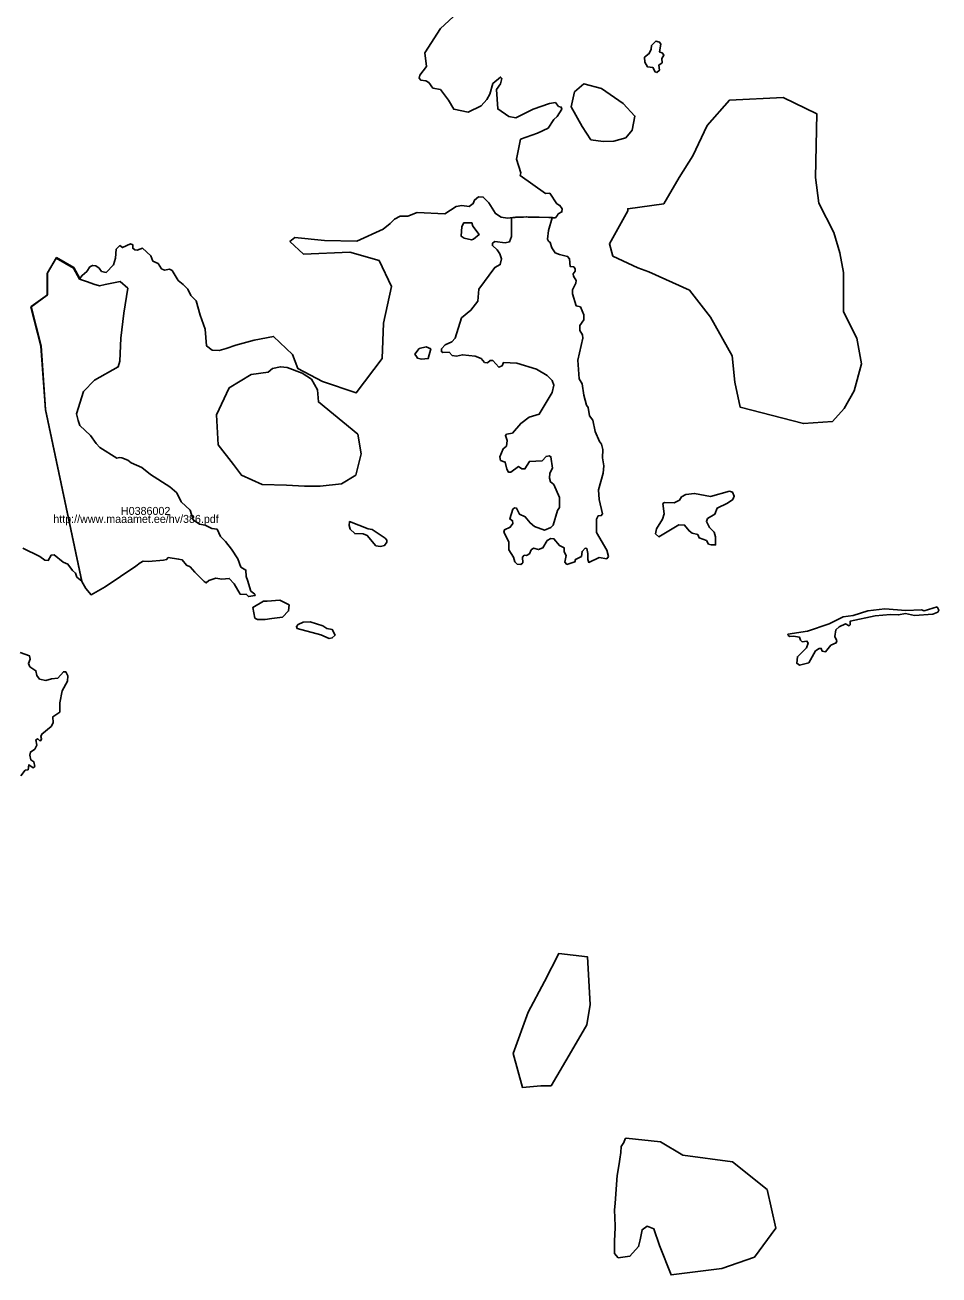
# Model space of a CAD drawing. Extents: x 369010 to 739155, y 6377141 to 6634081.
# Drawn here: x 449202 to 452056, y 6474923 to 6478828 of the extents above; entities that cross this region are included whole.
import ezdxf

# ---------------------------------------------------------------- set-up
doc = ezdxf.new("R2010")
doc.units = 0
for name, color, linetype in [('H_LINK', 7, 'Continuous'), ('H_PIIR', 7, 'Continuous'), ('H_TUNNUS', 7, 'Continuous')]:
    doc.layers.add(name, color=color, linetype=linetype)

msp = doc.modelspace()

# ---------------------------------------------------------------- linework, layer by layer
at = {"layer": 'H_PIIR'}
for points in [[(450579.291, 6478890.1741), (450499.9159, 6478817.4136), (450451.1638, 6478740.6622), (450455.7538, 6478698.1322), (450435.6438, 6478671.3221), (450432.9637, 6478662.1321), (450437.9438, 6478656.0022), (450454.0338, 6478654.0821), (450463.2238, 6478648.3422), (450476.2437, 6478630.3321), (450499.6138, 6478626.5022), (450524.8938, 6478593.5522), (450540.9264, 6478564.736), (450585.9839, 6478556.0122), (450626.3939, 6478575.5521), (450644.7837, 6478595.8622), (450654.3538, 6478611.5622), (450662.7839, 6478645.2821), (450687.2938, 6478665.5821), (450691.5137, 6478660.6022), (450687.2938, 6478644.5122), (450674.2739, 6478626.5022), (450678.51, 6478566.0589), (450713.3437, 6478542.6021), (450734.9838, 6478538.3821), (450788.9937, 6478565.5821), (450839.9061, 6478583.2568), (450858.427, 6478585.9027), (450868.6739, 6478573.6321), (450876.7137, 6478571.7122), (450878.2438, 6478565.5821), (450863.6938, 6478541.8322), (450853.3538, 6478532.6421), (450835.7337, 6478506.2021), (450802.2137, 6478489.7322), (450750.1138, 6478470.9621), (450737.2838, 6478409.2821), (450750.3137, 6478366.7622), (450748.7838, 6478357.5622), (450827.4938, 6478301.6422), (450840.8937, 6478302.7922), (450863.1138, 6478269.4622), (450872.6939, 6478264.4821), (450879.9638, 6478253.3721), (450878.8238, 6478244.1721), (450867.3238, 6478237.6622), (450864.7682, 6478234.0679), (450858.4182, 6478225.3366), (450848.9297, 6478226.0923), (450849.0221, 6478226.4048), (450843.2216, 6478226.547), (450838.4862, 6478226.9241), (450808.059, 6478227.5856), (450798.6339, 6478227.6397), (450773.6374, 6478228.2524), (450768.1069, 6478228.5116), (450758.5466, 6478228.2762), (450747.3452, 6478228.1151), (450744.5903, 6478227.8939), (450734.5047, 6478227.5856), (450708.7437, 6478224.6321), (450689.2037, 6478227.7022), (450671.9739, 6478238.8122), (450650.5237, 6478272.1422), (450633.2839, 6478290.5321), (450618.9239, 6478290.9121), (450605.9038, 6478281.3321), (450601.6838, 6478270.2221), (450589.0438, 6478261.4122), (450566.8337, 6478264.4721), (450548.8238, 6478260.6422), (450513.0138, 6478238.0421), (450427.2037, 6478242.2622), (450398.2937, 6478230.7722), (450373.7738, 6478230.3921), (450356.1538, 6478221.5822), (450342.7883, 6478207.7666), (450320.5633, 6478189.7749), (450238.0131, 6478152.7331), (450137.4712, 6478154.8498), (450045.3961, 6478164.3748), (450029.521, 6478151.6748), (450071.8544, 6478112.5164), (450216.8464, 6478118.8664), (450307.8632, 6478092.408), (450347.0217, 6478010.9162), (450321.6216, 6477896.616), (450317.3883, 6477786.5491), (450236.9548, 6477678.5989), (450131.1212, 6477714.5823), (450053.8627, 6477754.799), (450037.9877, 6477799.2491), (449978.7209, 6477855.3409), (449918.3958, 6477843.6992), (449860.1874, 6477827.8242), (449830.554, 6477817.2408), (449808.3289, 6477810.8908), (449787.1622, 6477811.9491), (449769.1705, 6477825.7075), (449764.9372, 6477877.5659), (449749.0621, 6477922.016), (449736.9738, 6477966.4322), (449719.7338, 6477982.9121), (449711.3039, 6478002.8322), (449696.3638, 6478017.7722), (449680.8538, 6478030.0322), (449662.0837, 6478060.6821), (449653.6638, 6478065.6622), (449637.5738, 6478062.2122), (449628.7639, 6478066.4321), (449617.6537, 6478082.5222), (449601.5637, 6478090.5622), (449594.8638, 6478106.6522), (449568.8239, 6478130.4022), (449552.7338, 6478125.0422), (449545.4538, 6478125.4221), (449538.9438, 6478130.4022), (449538.5538, 6478141.5121), (449532.0438, 6478144.9621), (449507.1538, 6478132.7022), (449498.7238, 6478138.8321), (449487.2338, 6478127.7221), (449484.5539, 6478099.7522), (449478.9938, 6478078.6721), (449455.6237, 6478054.9221), (449441.4538, 6478058.3721), (449433.7939, 6478067.9522), (449423.4538, 6478075.2221), (449413.1138, 6478077.1422), (449405.0638, 6478072.9321), (449395.1039, 6478058.3721), (449380.5537, 6478045.7321), (449373.4638, 6478036.1522), (449354.9038, 6478070.4775), (449300.9137, 6478101.7275), (449272.5038, 6478053.4276), (449272.5038, 6477985.2274), (449221.3537, 6477948.2774), (449252.6039, 6477826.0876), (449266.8138, 6477627.1775), (449380.2638, 6477091.0276), (449380.3405, 6477090.6648), (449379.6038, 6477090.2221), (449364.0838, 6477103.2522), (449359.8739, 6477115.5122), (449350.6839, 6477123.5522), (449336.5038, 6477144.2422), (449321.1837, 6477150.3721), (449293.6039, 6477172.5922), (449283.6437, 6477171.4422), (449274.8338, 6477155.3521), (449263.7338, 6477156.5022), (449248.9837, 6477167.9922), (449195.7438, 6477194.0521)], [(449187.7038, 6476868.0321), (449216.8239, 6476856.9222), (449218.5439, 6476846.9521), (449212.7939, 6476833.1622), (449217.0138, 6476823.2021), (449236.5438, 6476810.9421), (449238.8438, 6476796.3822), (449247.6538, 6476784.5121), (449267.5739, 6476780.2922), (449285.5738, 6476785.2722), (449304.7238, 6476787.5722), (449322.3439, 6476807.4921), (449330.0038, 6476807.1121), (449336.1337, 6476794.8521), (449334.6038, 6476778.3822), (449318.1338, 6476747.7321), (449311.4339, 6476710.9622), (449310.6638, 6476681.4622), (449289.5938, 6476667.2821), (449290.3638, 6476647.7421), (449283.8538, 6476637.0222), (449254.9339, 6476612.8922), (449251.8637, 6476604.8522), (449254.1637, 6476598.3322), (449252.2438, 6476593.3522), (449248.4137, 6476592.2022), (449242.2938, 6476598.3322), (449236.5438, 6476594.5022), (449239.6038, 6476578.7922), (449233.4837, 6476566.1522), (449219.3038, 6476556.5721), (449217.0038, 6476546.6122), (449220.8439, 6476532.4421), (449229.6538, 6476526.6921), (449233.4837, 6476512.1321), (449228.1138, 6476507.5421), (449214.3238, 6476517.1122), (449212.0337, 6476501.4122), (449203.2238, 6476500.6421), (449189.6237, 6476482.2521)]]:
    msp.add_lwpolyline(points, dxfattribs=at)
for points in [[(451174.9632, 6478679.4431), (451169.9981, 6478681.4292), (451163.0469, 6478695.166), (451145.8345, 6478697.4831), (451137.3938, 6478712.3784), (451136.5662, 6478727.2738), (451151.4616, 6478738.859), (451158.0819, 6478752.5959), (451158.7438, 6478764.0156), (451171.8186, 6478777.918), (451183.7349, 6478774.7734), (451187.5415, 6478768.3188), (451183.404, 6478744.4862), (451193.3341, 6478740.3485), (451197.4718, 6478734.225), (451191.3481, 6478723.4672), (451192.5066, 6478710.0614), (451181.7489, 6478702.7792), (451183.404, 6478686.7252)], [(450907.375, 6478572.6735), (450917.9584, 6478618.9757), (450947.0626, 6478644.1111), (451002.6252, 6478629.559), (451070.0941, 6478583.2568), (451107.1358, 6478543.5693), (451097.8754, 6478499.9129), (451078.0316, 6478476.1004), (451040.9899, 6478465.517), (451007.9169, 6478464.1941), (450969.5522, 6478469.4858), (450941.7709, 6478510.4963)], [(451196.8297, 6478268.9312), (451245.5132, 6478351.4814), (451287.8466, 6478419.2148), (451332.2967, 6478514.465), (451402.1468, 6478592.7819), (451569.3638, 6478601.2485), (451675.1974, 6478550.4484), (451670.964, 6478351.4814), (451681.5474, 6478271.0479), (451728.1141, 6478180.031), (451747.1642, 6478116.5309), (451757.7475, 6478055.1474), (451757.7475, 6477932.3805), (451800.081, 6477849.8304), (451814.8976, 6477769.3969), (451791.6143, 6477684.73), (451759.8642, 6477629.6966), (451723.8808, 6477589.4798), (451632.864, 6477583.1298), (451436.0136, 6477633.9299), (451419.0802, 6477712.2468), (451410.6135, 6477794.7969), (451342.88, 6477915.4472), (451277.2632, 6478000.114), (451150.263, 6478057.2641), (451116.3963, 6478069.9641), (451038.0794, 6478105.9475), (451027.4961, 6478144.0476), (451084.6462, 6478247.7645), (451084.6462, 6478254.1145)], [(450669.6796, 6478151.8163), (450701.4563, 6478147.1823), (450715.6896, 6478151.1544), (450721.0109, 6478166.8884), (450722.0031, 6478187.3936), (450721, 6478226), (450744.5903, 6478227.8939), (450751.0738, 6478228.0921), (450758.5466, 6478228.2762), (450767.4454, 6478228.4041), (450773.6374, 6478228.2524), (450785.0402, 6478227.7179), (450798.6339, 6478227.6397), (450843.2216, 6478226.547), (450848.9297, 6478226.0923), (450837.0971, 6478186.0707), (450833.7898, 6478159.2816), (450837.4278, 6478152.9977), (450842.1988, 6478148.8958), (450846.9984, 6478132.3454), (450857.7563, 6478116.788), (450871.493, 6478110.6643), (450896.4201, 6478105.1442), (450903.0402, 6478097.5311), (450904.8607, 6478073.3675), (450916.115, 6478072.2089), (450920.2526, 6478066.0853), (450920.2526, 6478059.1342), (450914.4599, 6478050.3625), (450915.2874, 6478043.0802), (450923.2317, 6478030.3364), (450922.9006, 6478021.5647), (450911.9773, 6478000.5456), (450911.9773, 6477988.6294), (450923.8936, 6477950.398), (450936.9685, 6477947.5844), (450947.2297, 6477922.4278), (450947.2297, 6477907.036), (450934.6514, 6477888.996), (450934.4859, 6477873.2731), (450943.5886, 6477860.3639), (450944.7472, 6477850.2681), (450928.1968, 6477780.9219), (450932.9964, 6477722.83), (450942.2646, 6477707.1071), (450946.8988, 6477671.3583), (450955.8359, 6477640.74), (450961.1321, 6477632.7959), (450965.4351, 6477606.6463), (450975.6964, 6477594.0679), (450982.9785, 6477557.988), (450995.8879, 6477527.0388), (451002.8391, 6477518.5981), (451006.6456, 6477501.7166), (451006.1492, 6477476.3945), (451010.1213, 6477451.0724), (451007.3076, 6477428.0674), (450993.4054, 6477375.6025), (450995.7225, 6477346.1429), (451005.6526, 6477300.9604), (451001.846, 6477295.4987), (450991.9158, 6477294.5057), (450986.9506, 6477284.41), (450987.1162, 6477242.3718), (451019.7205, 6477187.921), (451024.1891, 6477167.564), (451018.893, 6477160.7785), (450995.0604, 6477164.0885), (450962.9526, 6477149.1931), (450959.4771, 6477157.9648), (450960.3046, 6477177.4943), (450957.16, 6477192.5552), (450951.5327, 6477193.2172), (450941.9335, 6477183.618), (450939.6165, 6477168.0606), (450921.5765, 6477158.4614), (450919.2596, 6477150.6827), (450894.7649, 6477143.0694), (450887.6482, 6477150.3517), (450891.9514, 6477170.7086), (450885.8277, 6477181.7974), (450885.8277, 6477194.8722), (450871.2635, 6477202.1544), (450854.051, 6477223.1734), (450843.9552, 6477223.5044), (450832.5354, 6477217.3809), (450819.4607, 6477195.2033), (450806.0548, 6477189.0797), (450790.0008, 6477193.2172), (450783.3807, 6477188.2521), (450777.5882, 6477175.6738), (450768.3199, 6477170.7086), (450761.5342, 6477171.3706), (450755.4107, 6477166.0746), (450756.4036, 6477148.0347), (450750.7765, 6477142.7385), (450738.8603, 6477143.897), (450731.9091, 6477151.5102), (450728.1024, 6477165.247), (450713.2071, 6477188.2521), (450713.2071, 6477213.2431), (450697.8153, 6477244.1925), (450699.4703, 6477251.1437), (450717.8412, 6477259.5843), (450725.7854, 6477270.3421), (450725.1233, 6477279.1138), (450716.1862, 6477285.2375), (450726.1163, 6477315.1937), (450730.585, 6477320.1588), (450737.5362, 6477318.5037), (450746.3079, 6477299.8017), (450764.3478, 6477291.3612), (450779.7396, 6477272.6592), (450793.8075, 6477261.4049), (450824.4257, 6477249.9851), (450844.6173, 6477258.0947), (450851.8994, 6477265.377), (450865.6362, 6477311.718), (450871.7599, 6477320.4899), (450871.0978, 6477352.2666), (450853.5544, 6477392.1529), (450843.6243, 6477400.5937), (450839.8177, 6477412.8411), (450840.9761, 6477427.7364), (450849.7478, 6477443.4593), (450844.7827, 6477479.0427), (450839.4866, 6477482.5182), (450829.5564, 6477480.2011), (450817.1436, 6477466.4644), (450777.4227, 6477464.4782), (450763.1892, 6477441.1423), (450753.59, 6477441.1423), (450743.1633, 6477448.4244), (450719.3307, 6477431.212), (450712.0486, 6477431.212), (450706.7524, 6477440.4802), (450702.1183, 6477462.6577), (450687.5539, 6477467.6228), (450684.9059, 6477479.0427), (450695.9946, 6477504.3648), (450706.2559, 6477512.4744), (450708.242, 6477530.5144), (450702.4492, 6477545.4097), (450705.9249, 6477549.5473), (450724.2958, 6477552.6919), (450750.6111, 6477583.3101), (450776.9261, 6477603.1706), (450808.0408, 6477612.1079), (450848.7548, 6477680.2955), (450853.389, 6477702.8041), (450848.4239, 6477717.3683), (450832.3699, 6477733.0912), (450799.4346, 6477752.9517), (450737.8671, 6477772.1503), (450696.9876, 6477774.1362), (450692.3536, 6477763.0475), (450681.5958, 6477759.0754), (450662.8938, 6477779.929), (450654.4531, 6477779.929), (450646.84, 6477772.9778), (450637.2408, 6477773.6398), (450626.6484, 6477786.7145), (450607.9464, 6477793.3348), (450568.0601, 6477797.8033), (450550.0201, 6477793.9967), (450535.7868, 6477795.9828), (450527.0151, 6477805.9131), (450507.3201, 6477804.7545), (450502.686, 6477807.8991), (450503.1826, 6477816.6707), (450514.2713, 6477828.9181), (450534.9593, 6477838.0207), (450545.2205, 6477849.2751), (450565.2464, 6477912.8286), (450594.8717, 6477936.9922), (450616.7183, 6477965.6243), (450619.6972, 6478002.8627), (450669.3484, 6478070.7195), (450686.5609, 6478079.4912), (450690.3675, 6478097.8621), (450685.0713, 6478112.7574), (450676.9617, 6478125.5012), (450661.7354, 6478139.238), (450662.0663, 6478146.5203)], [(450566.0618, 6478198.5519), (450572.4118, 6478209.6644), (450597.8119, 6478209.6644), (450600.9869, 6478200.1394), (450620.0369, 6478173.1518), (450602.5744, 6478158.8643), (450596.2244, 6478157.2768), (450573.9993, 6478162.0393), (450564.4743, 6478168.3893)], [(449379.5467, 6477089.0773), (449379.47, 6477089.4401), (449266.02, 6477625.59), (449251.8101, 6477824.5001), (449220.5599, 6477946.6899), (449271.71, 6477983.6399), (449271.71, 6478051.8401), (449300.1199, 6478100.14), (449354.11, 6478068.89), (449372.7, 6478034.4899), (449372.7126, 6478034.4668), (449397.8939, 6478025.3184), (449417.7377, 6478018.9684), (449435.3841, 6478013.7056), (449452.6627, 6478017.3809), (449499.9571, 6478026.8728), (449523.1082, 6478005.7061), (449511.2019, 6477927.6539), (449501.0816, 6477850.1969), (449498.3034, 6477777.5687), (449492.7472, 6477760.1061), (449418.9283, 6477718.831), (449385.1938, 6477683.5091), (449362.9688, 6477612.8652), (449368.1282, 6477593.0214), (449373.15, 6477576.92), (449407.0126, 6477545.7221), (449424.38, 6477520.8046), (449436.2599, 6477508.1646), (449488.73, 6477475.2146), (449497.73, 6477477.1346), (449505.0099, 6477476.3746), (449523.78, 6477468.7047), (449533.3601, 6477459.8947), (449567.06, 6477445.3346), (449593.8799, 6477424.2647), (449654.6, 6477385.5647), (449676.4301, 6477366.7946), (449690.2199, 6477338.8247), (449717.8, 6477312.0146), (449726.99, 6477282.5146), (449747.1, 6477268.7246), (449765.11, 6477265.6647), (449786.17, 6477254.9346), (449801.88, 6477253.0246), (449812.6001, 6477230.0346), (449828.6899, 6477214.7147), (449847.2701, 6477190.1846), (449867.19, 6477160.3046), (449876.77, 6477134.6347), (449892.0899, 6477125.0546), (449892.47, 6477105.1347), (449897.03, 6477093.5047), (449907.7901, 6477059.5447), (449920.4299, 6477049.9646), (449920.82, 6477046.1346), (449900.52, 6477042.6846), (449894.3899, 6477049.2047), (449873.6999, 6477050.3447), (449855.3201, 6477082.5346), (449840.38, 6477099.3847), (449816.82, 6477097.0847), (449798.0499, 6477099.7646), (449776.6, 6477092.8646), (449768.1701, 6477085.2046), (449761.66, 6477089.8046), (449732.55, 6477118.9147), (449717.9901, 6477135.3946), (449706.5001, 6477140.3747), (449693.48, 6477157.2247), (449681.8, 6477159.5247), (449649.62, 6477164.1247), (449644.26, 6477157.9946), (449634.3001, 6477156.4647), (449588.1401, 6477152.2446), (449571.2899, 6477153.0147), (449561.9469, 6477147.5945), (449548.7177, 6477137.6726), (449452.806, 6477072.8495), (449408.4882, 6477048.3755), (449391.9518, 6477068.2193)], [(450432.7116, 6477817.5511), (450454.9366, 6477822.3136), (450469.2241, 6477815.9636), (450461.2866, 6477785.8011), (450440.6491, 6477784.2136), (450427.949, 6477787.3886), (450424.774, 6477792.1511), (450420.0115, 6477800.0886)], [(449961.2584, 6477743.1573), (449975.5459, 6477755.0636), (450000.1522, 6477760.6199), (450020.7898, 6477758.2386), (450067.8857, 6477740.2469), (450096.4607, 6477721.1969), (450116.0399, 6477687.8593), (450118.6858, 6477650.8176), (450241.9819, 6477549.7465), (450252.3006, 6477488.6276), (450235.6319, 6477421.9525), (450190.388, 6477394.4358), (450124.242, 6477387.8212), (450075.294, 6477387.8212), (450018.4085, 6477390.467), (449943.0021, 6477393.1129), (449878.1791, 6477422.2171), (449853.0436, 6477455.2901), (449805.4185, 6477516.1444), (449800.1268, 6477610.0716), (449839.8144, 6477694.7385), (449908.6062, 6477735.749)], [(451402.2001, 6477371.7961), (451411.6339, 6477368.3204), (451417.0955, 6477355.7421), (451412.4614, 6477346.1429), (451395.5801, 6477333.8957), (451363.8033, 6477319.0003), (451356.1901, 6477299.4708), (451333.1851, 6477286.065), (451330.0405, 6477277.1277), (451339.6397, 6477258.7568), (451354.204, 6477243.5305), (451358.5072, 6477229.6281), (451358.8381, 6477203.975), (451345.1013, 6477203.6439), (451336.9917, 6477206.623), (451330.0405, 6477217.3809), (451307.863, 6477225.4905), (451303.2289, 6477236.9102), (451286.0164, 6477240.0548), (451276.0861, 6477247.668), (451261.8528, 6477266.0389), (451243.9785, 6477266.8664), (451182.0799, 6477229.2971), (451171.6532, 6477238.5654), (451173.9702, 6477253.7917), (451193.1686, 6477284.0789), (451198.1337, 6477301.2913), (451194.3273, 6477332.7371), (451199.6233, 6477336.5437), (451229.2485, 6477335.3851), (451245.6335, 6477343.1638), (451252.5847, 6477353.7561), (451266.3214, 6477361.0383), (451293.464, 6477364.8449), (451343.1152, 6477355.4112)], [(450312.0254, 6477199.1754), (450298.2886, 6477201.4923), (450271.1459, 6477232.9381), (450258.4021, 6477238.5654), (450232.0869, 6477239.3929), (450217.5226, 6477253.1297), (450214.378, 6477264.3839), (450215.8676, 6477276.6313), (450274.125, 6477253.6262), (450286.8688, 6477251.6401), (450327.4172, 6477224.8285), (450332.3824, 6477219.0359), (450332.3824, 6477212.9122), (450325.1003, 6477202.32)], [(449947.3684, 6477027.7821), (449958.4809, 6477027.7821), (449998.1685, 6477030.9571), (450026.7436, 6477016.6696), (450025.1561, 6476997.6195), (450006.106, 6476978.5695), (449972.7685, 6476973.807), (449952.1309, 6476970.632), (449928.3184, 6476970.632), (449920.3808, 6476975.3945), (449914.0308, 6477008.732)], [(452050.3139, 6477010.1698), (452056.4376, 6477000.2395), (452052.631, 6476993.2883), (452036.9081, 6476987.4958), (451979.4782, 6476983.6891), (451951.6735, 6476989.1508), (451930.1579, 6476985.1787), (451905.3324, 6476986.0062), (451857.0053, 6476981.8686), (451778.7218, 6476965.3182), (451779.3838, 6476954.5604), (451776.0738, 6476951.0849), (451764.4884, 6476957.2084), (451744.628, 6476948.1058), (451733.8702, 6476938.5066), (451731.2222, 6476917.4875), (451737.0147, 6476904.4127), (451735.3597, 6476897.4616), (451719.1404, 6476890.1793), (451702.2589, 6476869.9879), (451691.1702, 6476872.305), (451688.8531, 6476880.7456), (451681.9019, 6476880.7456), (451671.3097, 6476872.6359), (451649.7943, 6476835.8942), (451620.4999, 6476827.7843), (451612.3903, 6476834.239), (451614.3764, 6476854.2651), (451643.0085, 6476882.5662), (451648.1391, 6476897.1305), (451644.167, 6476903.2542), (451629.2718, 6476901.4337), (451623.9756, 6476906.3988), (451621.3274, 6476915.5016), (451601.6324, 6476919.308), (451591.0403, 6476917.8186), (451585.2477, 6476920.9631), (451584.4202, 6476924.7697), (451645.9876, 6476934.369), (451713.0167, 6476957.705), (451757.3718, 6476979.5516), (451788.4866, 6476983.0271), (451834.6621, 6476998.2536), (451887.127, 6477004.3771), (451952.832, 6476998.75), (452001.8211, 6477000.5706), (452010.2619, 6476997.5915)], [(450151.8176, 6476911.3639), (450125.6678, 6476923.2801), (450052.1841, 6476943.1407), (450049.867, 6476948.9333), (450054.8322, 6476954.7259), (450071.3826, 6476962.3391), (450092.7326, 6476963.4976), (450132.2881, 6476951.2504), (450144.5353, 6476942.8096), (450161.7477, 6476939.3341), (450170.5194, 6476922.1217), (450161.7477, 6476913.35)], [(450824.1993, 6475839.8005), (450869.1786, 6475927.1132), (450959.1371, 6475916.5299), (450967.0746, 6475768.3629), (450956.4913, 6475704.8628), (450908.8662, 6475622.8418), (450845.366, 6475514.3624), (450813.616, 6475514.3624), (450755.4075, 6475509.0707), (450726.3033, 6475614.9043), (450773.9284, 6475744.5504)], [(451080.0317, 6475350.1046), (451186.3944, 6475338.992), (451256.2446, 6475297.717), (451411.8199, 6475277.0794), (451519.7701, 6475189.7667), (451546.7577, 6475069.1165), (451480.0825, 6474978.6288), (451378.4823, 6474943.7038), (451219.732, 6474923.0662), (451183.2194, 6475015.1414), (451165.7569, 6475067.529), (451145.1194, 6475075.4665), (451129.2443, 6475064.354), (451122.8943, 6475032.6039), (451118.1318, 6475011.9664), (451091.1443, 6474981.8038), (451054.6317, 6474977.0413), (451043.5192, 6474989.7413), (451043.5192, 6475029.4289), (451045.1067, 6475070.704), (451045.1067, 6475077.054), (451043.5192, 6475126.2666), (451045.1067, 6475146.9042), (451048.2817, 6475191.3543), (451051.4567, 6475234.2168), (451057.8067, 6475270.7294), (451059.3942, 6475285.0169), (451062.5692, 6475305.6545), (451064.1567, 6475324.7045), (451072.0942, 6475337.4045), (451076.8567, 6475348.5171)]]:
    msp.add_lwpolyline(points, close=True, dxfattribs=at)

# ---------------------------------------------------------------- texts
at = {"layer": 'H_LINK'}
msp.add_text('http://www.maaamet.ee/hv/386.pdf', height=25, rotation=360, dxfattribs=at).set_placement((449290.7156, 6477272.5748))
at = {"layer": 'H_TUNNUS'}
msp.add_text('H0386002', height=25, rotation=360, dxfattribs=at).set_placement((449501.9445, 6477297.5748))

doc.saveas('drawing.dxf')
